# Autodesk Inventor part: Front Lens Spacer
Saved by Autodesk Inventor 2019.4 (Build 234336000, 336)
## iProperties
Created: 2020-09
Part Number: Front Lens Spacer
Material: Generic
Document SubType Name: Modeling
Designer: Administrator
Density: 1 g/cm^3
Appearance: Default
Title: Front Lens Spacer
Author: Administrator
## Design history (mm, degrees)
feature "Body1"
body "Solid1"
